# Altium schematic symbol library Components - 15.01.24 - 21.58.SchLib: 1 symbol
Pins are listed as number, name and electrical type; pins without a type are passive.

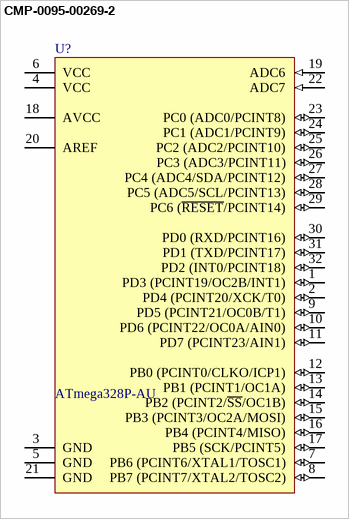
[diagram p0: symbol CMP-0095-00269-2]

## CMP-0095-00269-2
designator U?, comment ATmega328P-AU
8-bit AVR Microcontroller, 32KB Flash, 1KB EEPROM, 2KB SRAM, 32-pin TQFP, Industrial Grade (-40°C to 85°C)
footprint 32A_L (Thin QFP, 32-Leads, Body 7x7mm, Pitch 0.8mm, IPC High Density)
footprint 32A_N (Thin QFP, 32-Leads, Body 7x7mm, Pitch 0.8mm, IPC Medium Density)
footprint 32A_M (Thin QFP, 32-Leads, Body 7x7mm, Pitch 0.8mm, IPC Low Density)
pins: 1 PD3 (PCINT19/OC2B/INT1) (io), 2 PD4 (PCINT20/XCK/T0) (io), 3 GND (power), 4 VCC (power), 5 GND (power), 6 VCC (power), 7 PB6 (PCINT6/XTAL1/TOSC1) (io), 8 PB7 (PCINT7/XTAL2/TOSC2) (io), 9 PD5 (PCINT21/OC0B/T1) (io), 10 PD6 (PCINT22/OC0A/AIN0) (io), 11 PD7 (PCINT23/AIN1) (io), 12 PB0 (PCINT0/CLKO/ICP1) (io), 13 PB1 (PCINT1/OC1A) (io), 14 PB2 (PCINT2/~{SS}/OC1B) (io), 15 PB3 (PCINT3/OC2A/MOSI) (io), 16 PB4 (PCINT4/MISO) (io), 17 PB5 (SCK/PCINT5) (io), 18 AVCC (power), 19 ADC6 (in), 20 AREF, 21 GND (power), 22 ADC7 (in), 23 PC0 (ADC0/PCINT8) (io), 24 PC1 (ADC1/PCINT9) (io), 25 PC2 (ADC2/PCINT10) (io), 26 PC3 (ADC3/PCINT11) (io), 27 PC4 (ADC4/SDA/PCINT12) (io), 28 PC5 (ADC5/SCL/PCINT13) (io), 29 PC6 (~{RESET}/PCINT14) (io), 30 PD0 (RXD/PCINT16) (io), 31 PD1 (TXD/PCINT17) (io), 32 PD2 (INT0/PCINT18) (io)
